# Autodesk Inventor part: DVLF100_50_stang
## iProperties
Created: 2010-03
Part Number: DVLF100_50_stang
Document SubType Name: Modeling
Designer: TB
Mass: 733.813 g
Surface Area: 613.465 cm^2
Volume: 733.813 cm^3
Density: 1 g/cm^3
Author: TB
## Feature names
1. Revolution1
2. Fillet1
3. Revolution2
